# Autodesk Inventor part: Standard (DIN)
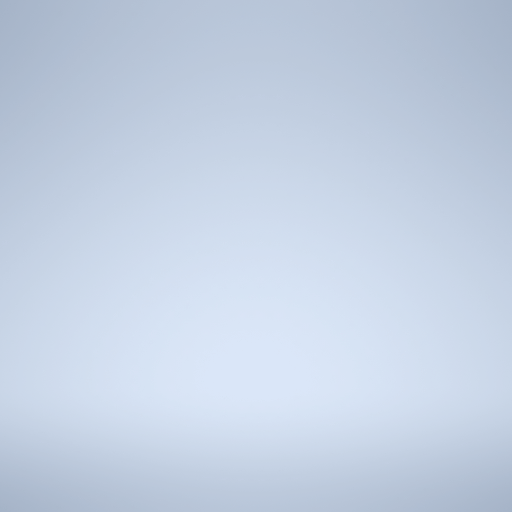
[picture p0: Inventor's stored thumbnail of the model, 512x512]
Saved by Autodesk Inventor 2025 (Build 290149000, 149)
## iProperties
Shininess: 64.0
Length Units: 11269
Angle Units: 11279
Time Units: 11290
Mass Units: 11283
Length Display Precision: 3
Angle Display Precision: 2
Compacted: True
Part Number: Standard (DIN)
Document SubType Name: Modeling
Created: 2002-07
Density: 1 g/cm^3
Material: Generico
Appearance: Default
Density: 0.0
Volumn: 0.0
Area: 0.0
PropertySet Name: Model Information
Control State: 0
Master: False
Checked Out: False
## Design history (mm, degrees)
